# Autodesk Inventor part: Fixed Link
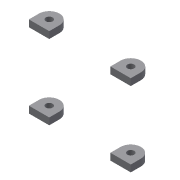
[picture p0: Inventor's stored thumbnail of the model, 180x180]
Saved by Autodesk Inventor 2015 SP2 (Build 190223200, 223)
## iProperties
Created: 2019-12
Part Number: Fixed Link
Material: 一般
Document SubType Name: Modeling
Designer: Kuan_Lun Hsu
Density: 1 g/cm^3
Appearance: 預設
Author: Kuan_Lun Hsu
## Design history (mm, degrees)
sketch "草圖1"
  geometry: L1 (-7.5, 0)-(7.5, 0); L2 (7.5, 0)-(7.5, -7.5); L3 (7.5, -7.5)-(-7.5, -7.5); L4 (-7.5, -7.5)-(-7.5, 0); C1 r 7.5 at (0, 0); 2 further points
  constraints: 8 end point, 2 coincident, 2 parallel, 2 tangent, 1 centre point, 1 horizontal, 1 midpoint, 1 perpendicular
  dimensions: "d0" = 15 diameter of C1
extrude "擠出1" new body sketch "草圖1" distance "d1" = 5; taper "d2" = 0 deg
sketch "草圖2"
  geometry: C1 r 2.5 at (0, 0); 1 further point
  constraints: 1 centre point, 1 coincident
  dimensions: "d3" = 5 diameter of C1
extrude "擠出2" cut sketch "草圖2" stored distance "d4" = 5; taper "d5" = 0 deg
pattern_linear "矩形陣列1"
pattern_linear "矩形陣列2" dims "d11" = 55
node "實體1"
